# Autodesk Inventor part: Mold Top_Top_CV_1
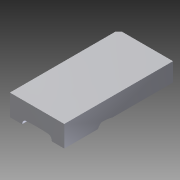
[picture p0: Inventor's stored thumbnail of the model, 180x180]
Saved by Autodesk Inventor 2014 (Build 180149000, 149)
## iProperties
Created: 2009-12
Part Number: Mold Top_Top_CV_1
Document SubType Name: Modeling
Designer: gaom
Density: 1 g/cm^3
Material: Generic
Appearance: Default
Author: gaom
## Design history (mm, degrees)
node "Mold Top_Top_CV_Base"
feature "Solid1::Mold Top_Top_CV_Base"
tag "TaggingFeature1"
body "Solid1"
